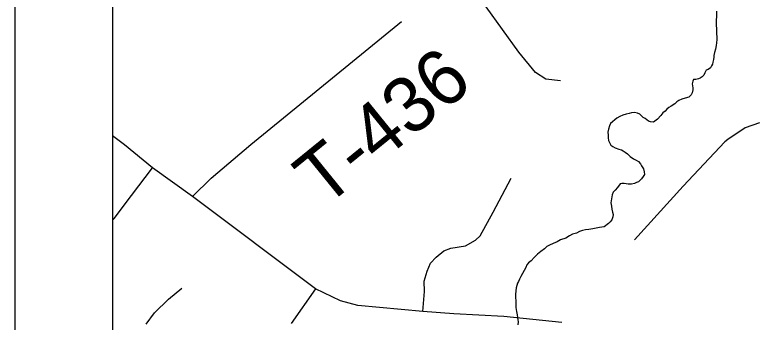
# Model space of a CAD drawing. Extents: x -59 to 82, y -3 to 49.
# Drawn here: x -54.998 to -54.242, y 43.01 to 43.325 of the extents above; entities that cross this region are included whole.
import ezdxf

# ---------------------------------------------------------------- set-up
doc = ezdxf.new("R2010")
doc.units = 0
for name, color, linetype in [('GM_X_Corporation', 7, 'Continuous'), ('GM_X_County_Road', 7, 'Continuous'), ('GM_X_Minor_River', 7, 'Continuous'), ('GM_X_Township_Road', 7, 'Continuous'), ('GM_X_Township_Road_Text', 7, 'Continuous'), ('SH_Data', 7, 'Continuous')]:
    doc.layers.add(name, color=color, linetype=linetype)

msp = doc.modelspace()

# ---------------------------------------------------------------- linework, layer by layer
at = {"layer": 'GM_X_Corporation'}
for p in [(-54.89799, 48.51547), (-54.89799, 43.46336)]:
    msp.add_line(p, (-54.89799, 42.49125), dxfattribs=at)
at = {"layer": 'GM_X_County_Road'}
for p, q in [((-54.88555, 43.19171), (-54.89799, 43.2009)), ((-54.85701, 43.1683), (-54.88555, 43.19171)), ((-54.8158, 43.13879), (-54.85701, 43.1683)), ((-54.68972, 43.04401), (-54.8158, 43.13879)), ((-54.66411, 43.0318), (-54.68972, 43.04401)), ((-54.64652, 43.02701), (-54.66411, 43.0318)), ((-54.57994, 43.02088), (-54.64652, 43.02701)), ((-54.5482, 43.0187), (-54.57994, 43.02088)), ((-54.49689, 43.01567), (-54.5482, 43.0187)), ((-54.43731, 43.00957), (-54.49689, 43.01567))]:
    msp.add_line(p, q, dxfattribs=at)
at = {"layer": 'GM_X_Minor_River'}
for p, q in [((-54.27893, 43.32413), (-54.27917, 43.31841)), ((-54.27905, 43.3287), (-54.27893, 43.32413)), ((-54.27917, 43.31841), (-54.27944, 43.31421)), ((-54.27944, 43.31421), (-54.27896, 43.31041)), ((-54.27896, 43.31041), (-54.27889, 43.30774)), ((-54.27889, 43.30774), (-54.27882, 43.30508)), ((-54.27869, 43.29975), (-54.27898, 43.29631)), ((-54.27882, 43.30508), (-54.27877, 43.30279)), ((-54.27877, 43.30279), (-54.27869, 43.29975)), ((-54.27929, 43.29363), (-54.27996, 43.2898)), ((-54.27898, 43.29631), (-54.27929, 43.29363)), ((-54.28101, 43.28635), (-54.2817, 43.28328)), ((-54.27996, 43.2898), (-54.28101, 43.28635)), ((-54.28197, 43.27908), (-54.28266, 43.2764)), ((-54.28165, 43.28138), (-54.28197, 43.27908)), ((-54.2817, 43.28328), (-54.28165, 43.28138)), ((-54.28518, 43.27061), (-54.28743, 43.26903)), ((-54.28409, 43.27255), (-54.28518, 43.27061)), ((-54.283, 43.27448), (-54.28409, 43.27255)), ((-54.28266, 43.2764), (-54.283, 43.27448)), ((-54.29185, 43.2632), (-54.2937, 43.26125)), ((-54.29077, 43.26552), (-54.29185, 43.2632)), ((-54.28969, 43.26821), (-54.29077, 43.26552)), ((-54.28743, 43.26903), (-54.28969, 43.26821)), ((-54.30311, 43.25682), (-54.30381, 43.25413)), ((-54.30381, 43.25413), (-54.30332, 43.24995)), ((-54.3024, 43.25874), (-54.30311, 43.25682)), ((-54.30012, 43.2588), (-54.3024, 43.25874)), ((-54.29746, 43.25925), (-54.30012, 43.2588)), ((-54.29558, 43.26006), (-54.29746, 43.25925)), ((-54.2937, 43.26125), (-54.29558, 43.26006)), ((-54.30327, 43.24805), (-54.30395, 43.24498)), ((-54.30332, 43.24995), (-54.30327, 43.24805)), ((-54.31105, 43.23947), (-54.31446, 43.23862)), ((-54.30728, 43.2407), (-54.31105, 43.23947)), ((-54.30505, 43.24305), (-54.30728, 43.2407)), ((-54.30395, 43.24498), (-54.30505, 43.24305)), ((-54.32532, 43.23148), (-54.32795, 43.22989)), ((-54.32158, 43.23386), (-54.32532, 43.23148)), ((-54.31972, 43.23581), (-54.32158, 43.23386)), ((-54.31747, 43.23702), (-54.31972, 43.23581)), ((-54.31446, 43.23862), (-54.31747, 43.23702)), ((-54.36856, 43.2239), (-54.37158, 43.22306)), ((-54.3659, 43.22435), (-54.36856, 43.2239)), ((-54.36287, 43.22481), (-54.3659, 43.22435)), ((-54.3598, 43.22413), (-54.36287, 43.22481)), ((-54.35749, 43.22304), (-54.3598, 43.22413)), ((-54.3339, 43.2244), (-54.33612, 43.22168)), ((-54.33167, 43.22636), (-54.3339, 43.2244)), ((-54.32981, 43.22832), (-54.33167, 43.22636)), ((-54.32795, 43.22989), (-54.32981, 43.22832)), ((-54.38101, 43.21901), (-54.38772, 43.21351)), ((-54.378, 43.22061), (-54.38101, 43.21901)), ((-54.37499, 43.22222), (-54.378, 43.22061)), ((-54.37158, 43.22306), (-54.37499, 43.22222)), ((-54.35397, 43.2197), (-54.35749, 43.22304)), ((-54.35204, 43.21861), (-54.35397, 43.2197)), ((-54.34855, 43.21603), (-54.35204, 43.21861)), ((-54.33946, 43.21816), (-54.34357, 43.21501)), ((-54.33612, 43.22168), (-54.33946, 43.21816)), ((-54.38843, 43.2112), (-54.38948, 43.20775)), ((-54.38772, 43.21351), (-54.38843, 43.2112)), ((-54.34662, 43.21531), (-54.34855, 43.21603)), ((-54.34357, 43.21501), (-54.34662, 43.21531)), ((-54.38948, 43.20775), (-54.39016, 43.20468)), ((-54.39016, 43.20468), (-54.39008, 43.20163)), ((-54.39008, 43.20163), (-54.39002, 43.19897)), ((-54.39002, 43.19897), (-54.38957, 43.19631)), ((-54.38957, 43.19631), (-54.38875, 43.19404)), ((-54.38875, 43.19404), (-54.38716, 43.19142)), ((-54.38716, 43.19142), (-54.38522, 43.18994)), ((-54.38522, 43.18994), (-54.38289, 43.18848)), ((-54.38289, 43.18848), (-54.37905, 43.18743)), ((-54.37905, 43.18743), (-54.37637, 43.18674)), ((-54.37637, 43.18674), (-54.37444, 43.18564)), ((-54.37444, 43.18564), (-54.3725, 43.18417)), ((-54.3725, 43.18417), (-54.37016, 43.18232)), ((-54.37016, 43.18232), (-54.36743, 43.17972)), ((-54.36743, 43.17972), (-54.36394, 43.17752)), ((-54.36394, 43.17752), (-54.36124, 43.17607)), ((-54.36124, 43.17607), (-54.35892, 43.1746)), ((-54.35892, 43.1746), (-54.35696, 43.17236)), ((-54.35696, 43.17236), (-54.35576, 43.17011)), ((-54.35576, 43.17011), (-54.35377, 43.16711)), ((-54.35377, 43.16711), (-54.35293, 43.16408)), ((-54.35293, 43.16408), (-54.35287, 43.16142)), ((-54.35579, 43.15677), (-54.35876, 43.15364)), ((-54.35395, 43.1591), (-54.35579, 43.15677)), ((-54.35287, 43.16142), (-54.35395, 43.1591)), ((-54.37776, 43.15164), (-54.38034, 43.14814)), ((-54.37586, 43.15207), (-54.37776, 43.15164)), ((-54.37358, 43.15213), (-54.37586, 43.15207)), ((-54.37167, 43.15179), (-54.37358, 43.15213)), ((-54.36937, 43.15147), (-54.37167, 43.15179)), ((-54.36595, 43.15156), (-54.36937, 43.15147)), ((-54.36291, 43.15201), (-54.36595, 43.15156)), ((-54.36104, 43.15321), (-54.36291, 43.15201)), ((-54.35876, 43.15364), (-54.36104, 43.15321)), ((-54.38478, 43.14307), (-54.38585, 43.14038)), ((-54.38293, 43.14541), (-54.38478, 43.14307)), ((-54.38034, 43.14814), (-54.38293, 43.14541)), ((-54.38684, 43.13426), (-54.38717, 43.13234)), ((-54.38585, 43.14038), (-54.38684, 43.13426)), ((-54.38717, 43.13234), (-54.3867, 43.12893)), ((-54.3867, 43.12893), (-54.38625, 43.12589)), ((-54.38625, 43.12589), (-54.3854, 43.12286)), ((-54.3854, 43.12286), (-54.38496, 43.1202)), ((-54.38496, 43.1202), (-54.38528, 43.11791)), ((-54.38967, 43.11094), (-54.39416, 43.10777)), ((-54.38782, 43.11289), (-54.38967, 43.11094)), ((-54.38634, 43.11483), (-54.38782, 43.11289)), ((-54.38528, 43.11791), (-54.38634, 43.11483)), ((-54.41615, 43.10379), (-54.41918, 43.10295)), ((-54.41313, 43.10463), (-54.41615, 43.10379)), ((-54.40971, 43.10509), (-54.41313, 43.10463)), ((-54.40553, 43.10558), (-54.40971, 43.10509)), ((-54.40213, 43.10643), (-54.40553, 43.10558)), ((-54.39871, 43.1069), (-54.40213, 43.10643)), ((-54.39416, 43.10777), (-54.39871, 43.1069)), ((-54.43348, 43.09611), (-54.43877, 43.09445)), ((-54.42973, 43.09849), (-54.43348, 43.09611)), ((-54.42635, 43.1001), (-54.42973, 43.09849)), ((-54.42257, 43.10134), (-54.42635, 43.1001)), ((-54.41918, 43.10295), (-54.42257, 43.10134)), ((-54.45006, 43.08883), (-54.45269, 43.08762)), ((-54.44629, 43.09045), (-54.45006, 43.08883)), ((-54.44215, 43.09245), (-54.44629, 43.09045)), ((-54.43877, 43.09445), (-54.44215, 43.09245)), ((-54.45904, 43.0825), (-54.4624, 43.07975)), ((-54.4553, 43.08526), (-54.45904, 43.0825)), ((-54.45269, 43.08762), (-54.4553, 43.08526)), ((-54.46574, 43.07623), (-54.46869, 43.07273)), ((-54.4624, 43.07975), (-54.46574, 43.07623)), ((-54.47424, 43.06611), (-54.47606, 43.06301)), ((-54.47317, 43.0688), (-54.47424, 43.06611)), ((-54.47169, 43.07075), (-54.47317, 43.0688)), ((-54.46869, 43.07273), (-54.47169, 43.07075)), ((-54.47789, 43.05992), (-54.47933, 43.05683)), ((-54.47606, 43.06301), (-54.47789, 43.05992)), ((-54.48187, 43.05181), (-54.48297, 43.04988)), ((-54.48079, 43.05413), (-54.48187, 43.05181)), ((-54.47933, 43.05683), (-54.48079, 43.05413)), ((-54.48437, 43.04527), (-54.48468, 43.04222)), ((-54.48367, 43.04758), (-54.48437, 43.04527)), ((-54.48297, 43.04988), (-54.48367, 43.04758)), ((-54.48468, 43.04222), (-54.48496, 43.0384)), ((-54.48496, 43.0384), (-54.48472, 43.02888)), ((-54.48472, 43.02888), (-54.48462, 43.02507)), ((-54.48462, 43.02507), (-54.48375, 43.0209)), ((-54.48375, 43.0209), (-54.48328, 43.01748)), ((-54.48328, 43.01748), (-54.48283, 43.01483)), ((-54.48283, 43.01483), (-54.4824, 43.01255)), ((-54.4824, 43.01255), (-54.48233, 43.01027)), ((-54.48233, 43.01027), (-54.48264, 43.00721))]:
    msp.add_line(p, q, dxfattribs=at)
at = {"layer": 'GM_X_Township_Road'}
for p, q in [((-54.48144, 43.28674), (-54.5151, 43.33304)), ((-54.75609, 43.19222), (-54.60185, 43.31804)), ((-54.46431, 43.26599), (-54.48144, 43.28674)), ((-54.45379, 43.25907), (-54.46431, 43.26599)), ((-54.43875, 43.25727), (-54.45379, 43.25907)), ((-54.24968, 43.20924), (-54.2672, 43.19711)), ((-54.23498, 43.21424), (-54.24968, 43.20924)), ((-54.27037, 43.19484), (-54.31295, 43.1492)), ((-54.2672, 43.19711), (-54.27037, 43.19484)), ((-54.79661, 43.15766), (-54.75609, 43.19222)), ((-54.8783, 43.13995), (-54.85701, 43.1683)), ((-54.8158, 43.13879), (-54.79661, 43.15766)), ((-54.50771, 43.12265), (-54.48951, 43.15746)), ((-54.31295, 43.1492), (-54.36296, 43.09439)), ((-54.89621, 43.11606), (-54.8783, 43.13995)), ((-54.52107, 43.09839), (-54.50771, 43.12265)), ((-54.89799, 43.11439), (-54.89621, 43.11606)), ((-54.52602, 43.09395), (-54.52107, 43.09839)), ((-54.55125, 43.08577), (-54.53624, 43.08819)), ((-54.53624, 43.08819), (-54.52602, 43.09395)), ((-54.56619, 43.07671), (-54.55827, 43.08314)), ((-54.55827, 43.08314), (-54.55125, 43.08577)), ((-54.57192, 43.07029), (-54.56619, 43.07671)), ((-54.57559, 43.06226), (-54.57192, 43.07029)), ((-54.57835, 43.05193), (-54.57559, 43.06226)), ((-54.57812, 43.04137), (-54.57835, 43.05193)), ((-54.84041, 43.03362), (-54.82672, 43.04484)), ((-54.68972, 43.04401), (-54.71472, 43.00879)), ((-54.57994, 43.02088), (-54.57812, 43.04137)), ((-54.85475, 43.01946), (-54.84041, 43.03362)), ((-54.86341, 43.00787), (-54.85475, 43.01946))]:
    msp.add_line(p, q, dxfattribs=at)
at = {"layer": 'SH_Data'}
for p, q in [((-54.99799, 49.39125), (-54.99799, 42.39125)), ((-54.89799, 49.29125), (-54.89799, 42.49125))]:
    msp.add_line(p, q, dxfattribs=at)

# ---------------------------------------------------------------- texts
at = {"layer": 'GM_X_Township_Road_Text'}
msp.add_text('T-436', height=0.056818, rotation=39.05341, dxfattribs=at).set_placement((-54.68103, 43.12633))

doc.saveas('drawing.dxf')
